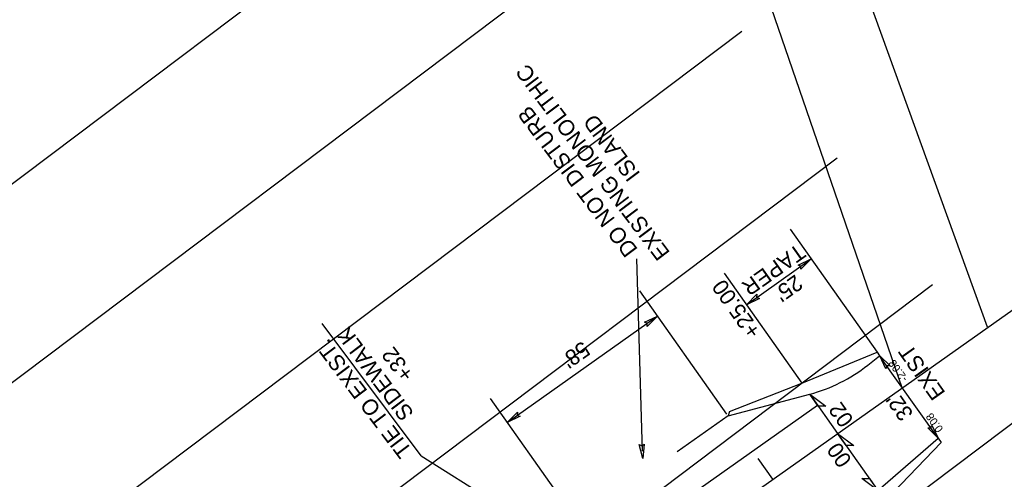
# Model space of a CAD drawing. Extents: x 1262309 to 1264352, y 775189 to 777755.
# Drawn here: x 1263383.2 to 1263693.6, y 776734.6 to 776879.5 of the extents above; entities that cross this region are included whole.
import ezdxf

# ---------------------------------------------------------------- set-up
doc = ezdxf.new("R2010")
doc.units = 0
for name, color, linetype in [('Prop Dimension', 7, 'Continuous'), ('Prop Dimension Text', 7, 'Continuous'), ('Prop EOT', 7, 'Continuous'), ('Prop Horizontal Alignment', 7, 'Continuous'), ('Prop Horizontal Alignment Station Label', 7, 'Continuous'), ('Prop Horizontal Alignment Tick Large', 7, 'Continuous'), ('Prop Lane Lines', 7, 'Continuous'), ('Prop Paved Shoulder', 7, 'Continuous'), ('Prop Superelevation  Arrow CELL', 7, 'Continuous'), ('Prop Superelevation Label', 7, 'Continuous'), ('Prop Terminator CELL', 7, 'Continuous'), ('Scratch_Level_0', 7, 'Continuous'), ('Scratch_Level_3', 7, 'Continuous')]:
    doc.layers.add(name, color=color, linetype=linetype)

msp = doc.modelspace()

# ---------------------------------------------------------------- linework, layer by layer
at = {"layer": 'Prop Dimension'}
for p, q in [((1263626.08, 776813.49), (1263653.57, 776774.66)), ((1263612.32, 776789.66), (1263632.73, 776804.1)), ((1263605.25, 776799.65), (1263629.82, 776764.93)), ((1263578.58, 776794.01), (1263606.06, 776755.18)), ((1263536.89, 776752.54), (1263584.22, 776786.04)), ((1263672.75, 776747.55), (1263654.32, 776773.58)), ((1263531.55, 776760.08), (1263559.04, 776721.24))]:
    msp.add_line(p, q, dxfattribs=at)
at = {"layer": 'Prop Dimension Text'}
for p, q in [((1263577.64, 776804.08), (1263579.4, 776743.44)), ((1263509.79, 776742.02), (1263478.5, 776783.68)), ((1263509.79, 776742.02), (1263549.53, 776716.98))]:
    msp.add_line(p, q, dxfattribs=at)
msp.add_lwpolyline([(1263580.06, 776745.72), (1263579.64, 776741.17), (1263578.49, 776745.62), (1263579.33, 776745.11)], close=True, dxfattribs=at)
at = {"layer": 'Prop EOT'}
for p, q in [((1263650.57, 776770.6), (1263654.32, 776773.58)), ((1263672.75, 776747.55), (1263654.32, 776773.58)), ((1263606.51, 776754.62), (1263632.29, 776761.44)), ((1263606.51, 776754.62), (1263590.43, 776743.24)), ((1263653.77, 776731.09), (1263672.75, 776747.55))]:
    msp.add_line(p, q, dxfattribs=at)
msp.add_arc((1263619.5, 776809.78), 50, 284.8258, 308.4134, dxfattribs=at)
at = {"layer": 'Prop Horizontal Alignment'}
msp.add_line((1263049.28, 776330.22), (1263743.09, 776821.26), dxfattribs=at)
at = {"layer": 'Prop Horizontal Alignment Station Label'}
for p, q in [((1263688.32, 776782.53), (1263633.68, 776933.72)), ((1263661.47, 776763.49), (1263607.44, 776920.38))]:
    msp.add_line(p, q, dxfattribs=at)
at = {"layer": 'Prop Horizontal Alignment Tick Large'}
msp.add_line((1263620.66, 776734.61), (1263616.03, 776741.14), dxfattribs=at)
at = {"layer": 'Prop Lane Lines'}
msp.add_line((1263533.22, 776686.2), (1263634.71, 776758.03), dxfattribs=at)
at = {"layer": 'Prop Paved Shoulder'}
for p, q in [((1263629.82, 776764.93), (1263653.57, 776774.66)), ((1263653.57, 776774.66), (1263654.32, 776773.58)), ((1263607, 776755.99), (1263629.82, 776764.93)), ((1263607, 776755.99), (1263606.51, 776754.62)), ((1263672.75, 776747.55), (1263673.7, 776746.21)), ((1263673.7, 776746.21), (1263656.08, 776727.82))]:
    msp.add_line(p, q, dxfattribs=at)
at = {"layer": 'Prop Superelevation  Arrow CELL'}
for p, q in [((1263632.29, 776761.44), (1263641.07, 776749.04)), ((1263641.07, 776749.04), (1263653.77, 776731.09))]:
    msp.add_line(p, q, dxfattribs=at)
for points in [[(1263632.29, 776761.44), (1263637.39, 776757.7), (1263634.96, 776757.67)], [(1263641.06, 776749.05), (1263646.16, 776745.31), (1263643.73, 776745.27)], [(1263653.77, 776731.09), (1263648.67, 776734.83), (1263651.1, 776734.86)]]:
    msp.add_lwpolyline(points, close=True, dxfattribs=at)
at = {"layer": 'Prop Terminator CELL'}
for points in [[(1263628.6, 776802.13), (1263632.73, 776804.1), (1263629.49, 776800.83), (1263629.5, 776801.82)], [(1263616.44, 776791.63), (1263612.32, 776789.66), (1263615.55, 776792.93), (1263615.54, 776791.94)], [(1263580.14, 776784.12), (1263584.26, 776786.08), (1263581.03, 776782.82), (1263581.04, 776783.8)], [(1263656.29, 776769.46), (1263654.33, 776773.58), (1263657.59, 776770.35), (1263656.61, 776770.36)], [(1263540.97, 776754.46), (1263536.85, 776752.49), (1263540.08, 776755.76), (1263540.07, 776754.77)], [(1263670.8, 776751.68), (1263672.75, 776747.55), (1263669.5, 776750.79), (1263670.48, 776750.78)]]:
    msp.add_lwpolyline(points, close=True, dxfattribs=at)
at = {"layer": 'Scratch_Level_3'}
for p, q in [((1263055.58, 776582.84), (1263550.68, 776955.75)), ((1263085.66, 776542.9), (1263580.76, 776915.82)), ((1263115.74, 776502.96), (1263610.84, 776875.88)), ((1263145.82, 776463.02), (1263640.93, 776835.94)), ((1263175.91, 776423.09), (1263671.01, 776796)), ((1263205.99, 776383.15), (1263701.09, 776756.06))]:
    msp.add_line(p, q, dxfattribs=at)

# ---------------------------------------------------------------- texts
at = {"layer": 'Prop Dimension'}
for s, rotation, p in [('EXISTING MONOLITHIC ', 127.0213, (1263588.42, 776806.05)), ('DO NOT DISTURB ', 127.0213, (1263578.25, 776807.08)), ('ISLAND', 127.0213, (1263579.05, 776830.93)), ('TAPER', 215.2883, (1263628.54, 776809.12)), ("25' ", 215.2883, (1263627.73, 776799.36)), ('SIDEWALK', 127.0213, (1263507.68, 776755.47)), ('TIE TO EXIST.', 127.0213, (1263507.13, 776743.74)), ('+32', 127.0213, (1263507.8, 776767.77)), ("58'", 215.2883, (1263560.64, 776778.39)), ("32'", 125.0259, (1263665.13, 776755.3))]:
    msp.add_text(s, height=5, rotation=rotation, dxfattribs=at).set_placement(p)
at = {"layer": 'Prop Dimension Text'}
msp.add_text('+25.00', height=5, rotation=125.2883, dxfattribs=at).set_placement((1263617.14, 776781.25))
at = {"layer": 'Prop Superelevation  Arrow CELL'}
msp.add_text('EXIST', height=5, rotation=125.2883, dxfattribs=at).set_placement((1263675.22, 776761.86))
at = {"layer": 'Prop Superelevation Label'}
for s, p in [('02', (1263646.32, 776753.34)), ('00', (1263645.74, 776740.64))]:
    msp.add_text(s, height=5, rotation=125.2883, dxfattribs=at).set_placement(p)
at = {"layer": 'Scratch_Level_0'}
for s, p in [('-2.08', (1263663.35, 776766.39)), ('0.08', (1263674.5, 776750.48))]:
    msp.add_text(s, height=2.5, rotation=125.2883, dxfattribs=at).set_placement(p)

doc.saveas('drawing.dxf')
